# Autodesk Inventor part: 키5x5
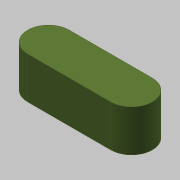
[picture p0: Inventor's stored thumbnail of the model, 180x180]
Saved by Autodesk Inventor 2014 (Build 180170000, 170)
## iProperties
Created: 2011-04
Part Number: 키5x5
Document SubType Name: Modeling
Designer: pww
Density: 7.86 g/cm^3
Material: 강철, 연강
Appearance: 올리브 녹색
Author: pww
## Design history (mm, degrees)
sketch "스케치1"
  geometry: L1 (-5, -2.5)-(5, -2.5); L2 (5, 2.5)-(-5, 2.5); A1 r 2.5 centre (-5, 0) between (-5, 2.5) and (-5, -2.5); A2 r 2.5 centre (5, 0) between (5, -2.5) and (5, 2.5); 1 further point
  constraints: 4 end point, 4 point on circle, 2 centre point
extrude "돌출1" new body sketch "스케치1" distance "d0" = 5; taper "d1" = 0 deg
node "솔리드1"
